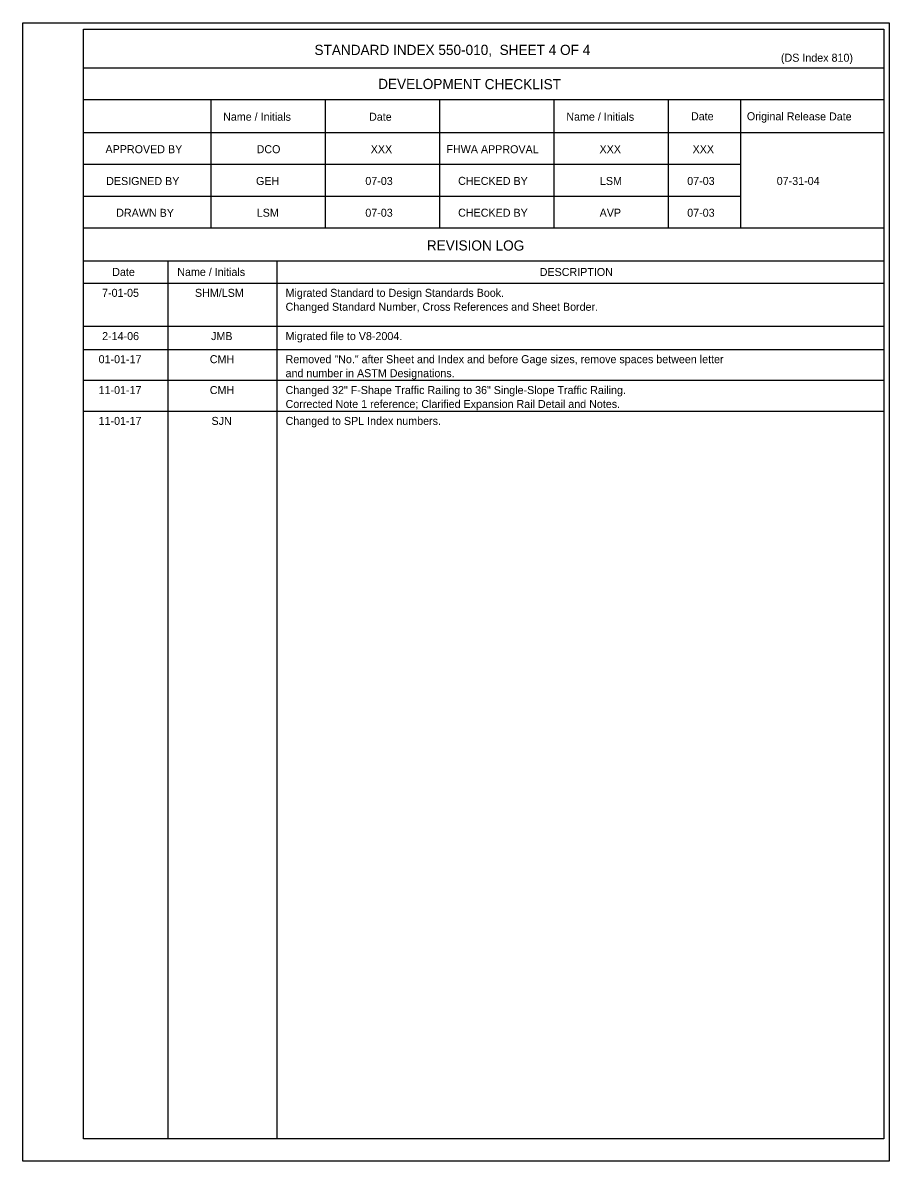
# Model space of a CAD drawing. Extents: x 110698 to 110915, y 110390 to 110472.
# Drawn here: x 110824.36 to 110846.17, y 110436.15 to 110464.82 of the extents above; entities that cross this region are included whole.
import ezdxf

# ---------------------------------------------------------------- set-up
doc = ezdxf.new("R2010")
doc.units = 0
doc.layers.add('Border', color=7, linetype='Continuous')
doc.layers.add('PlotBorder_dp', color=7, linetype='Continuous')

msp = doc.modelspace()

# ---------------------------------------------------------------- linework, layer by layer
at = {"layer": 'Border'}
for p, q in [((110846.038, 110463.673), (110825.891, 110463.673)), ((110846.038, 110462.873), (110825.891, 110462.873)), ((110829.091, 110462.873), (110829.091, 110459.645)), ((110831.971, 110462.873), (110831.971, 110459.645)), ((110834.851, 110462.873), (110834.851, 110459.645)), ((110837.731, 110462.873), (110837.731, 110459.645)), ((110840.611, 110462.873), (110840.611, 110459.645)), ((110842.426, 110462.873), (110842.426, 110459.645)), ((110846.038, 110462.045), (110825.891, 110462.045)), ((110842.426, 110461.245), (110825.891, 110461.245)), ((110842.426, 110460.445), (110825.891, 110460.445)), ((110846.038, 110459.645), (110825.891, 110459.645)), ((110846.038, 110458.817), (110825.891, 110458.817)), ((110828.011, 110458.817), (110828.011, 110436.711)), ((110830.754, 110458.817), (110830.754, 110436.711)), ((110846.038, 110458.253), (110825.891, 110458.253)), ((110846.038, 110457.164), (110825.891, 110457.164)), ((110846.038, 110456.582), (110825.891, 110456.582)), ((110846.038, 110455.805), (110825.891, 110455.805)), ((110846.038, 110455.028), (110825.891, 110455.028))]:
    msp.add_line(p, q, dxfattribs=at)
msp.add_lwpolyline([(110825.891, 110464.653), (110846.038, 110464.653), (110846.038, 110436.711), (110825.891, 110436.711)], close=True, dxfattribs=at)
at = {"layer": 'PlotBorder_dp'}
msp.add_line((110824.361, 110436.149), (110824.361, 110436.149), dxfattribs=at)
msp.add_lwpolyline([(110824.361, 110464.816), (110846.174, 110464.816), (110846.174, 110436.149), (110824.361, 110436.149)], close=True, dxfattribs=at)

# ---------------------------------------------------------------- texts
at = {"layer": 'Border'}
for s, height, p in [('STANDARD INDEX 550-010,  SHEET 4 OF 4', 0.256, (110831.704, 110464.005)), ('(DS Index 810)', 0.2016, (110843.448, 110463.835)), ('DCO', 0.2016, (110830.248, 110461.532)), ('XXX', 0.2016, (110833.121, 110461.532)), ('XXX', 0.2016, (110838.881, 110461.532)), ('XXX', 0.2016, (110841.224, 110461.532)), ('GEH', 0.2016, (110830.233, 110460.732)), ('07-03', 0.2016, (110832.985, 110460.732)), ('LSM', 0.2016, (110838.891, 110460.732)), ('07-03', 0.2016, (110841.089, 110460.732)), ('07-31-04', 0.2016, (110843.342, 110460.732)), ('LSM', 0.2016, (110830.251, 110459.932)), ('07-03', 0.2016, (110832.985, 110459.932)), ('AVP', 0.2016, (110838.884, 110459.932)), ('07-03', 0.2016, (110841.089, 110459.932)), ('DESCRIPTION', 0.2016, (110837.375, 110458.44)), ('7-01-05', 0.2016, (110826.357, 110457.915)), ('SHM/LSM', 0.2016, (110828.695, 110457.915)), ('Migrated Standard to Design Standards Book.', 0.2016, (110830.977, 110457.915)), ('Changed Standard Number, Cross References and Sheet Border.', 0.2016, (110830.977, 110457.564)), ('Migrated file to V8-2004.', 0.2016, (110830.977, 110456.826)), ('2-14-06', 0.2016, (110826.358, 110456.826)), ('JMB', 0.2016, (110829.101, 110456.826)), ('01-01-17', 0.2016, (110826.27, 110456.244)), ('CMH', 0.2016, (110829.069, 110456.244)), ('Removed "No." after Sheet and Index and before Gage sizes, remove spaces between letter', 0.2016, (110830.977, 110456.244)), ('and number in ASTM Designations.', 0.2016, (110830.977, 110455.892)), ('11-01-17', 0.2016, (110826.27, 110455.467)), ('CMH', 0.2016, (110829.069, 110455.467)), ('Changed 32" F-Shape Traffic Railing to 36" Single-Slope Traffic Railing.', 0.2016, (110830.977, 110455.467)), ('Corrected Note 1 reference; Clarified Expansion Rail Detail and Notes.', 0.2016, (110830.977, 110455.116)), ('11-01-17', 0.2016, (110826.27, 110454.69)), ('SJN', 0.2016, (110829.112, 110454.69)), ('Changed to SPL Index numbers.', 0.2016, (110830.977, 110454.69))]:
    msp.add_text(s, height=height, dxfattribs=at).set_placement(p)
for s, height, p in [('DEVELOPMENT CHECKLIST', 0.256, (110833.307, 110463.15)), ('Name / Initials', 0.2016, (110829.404, 110462.352)), ('Date', 0.2016, (110833.078, 110462.35)), ('Name / Initials', 0.2016, (110838.044, 110462.352)), ('Date', 0.2016, (110841.183, 110462.362)), ('Original Release Date', 0.2016, (110842.59, 110462.362)), ('APPROVED BY', 0.2016, (110826.443, 110461.534)), ('FHWA APPROVAL', 0.2016, (110835.026, 110461.534)), ('DESIGNED BY', 0.2016, (110826.46, 110460.732)), ('CHECKED BY', 0.2016, (110835.321, 110460.734)), ('DRAWN BY', 0.2016, (110826.713, 110459.932)), ('CHECKED BY', 0.2016, (110835.321, 110459.934)), ('REVISION LOG', 0.256, (110834.532, 110459.084)), ('Date', 0.2016, (110826.613, 110458.441)), ('Name / Initials', 0.2016, (110828.25, 110458.443))]:
    msp.add_text(s, height=height, rotation=359.8756, dxfattribs=at).set_placement(p)

doc.saveas('drawing.dxf')
